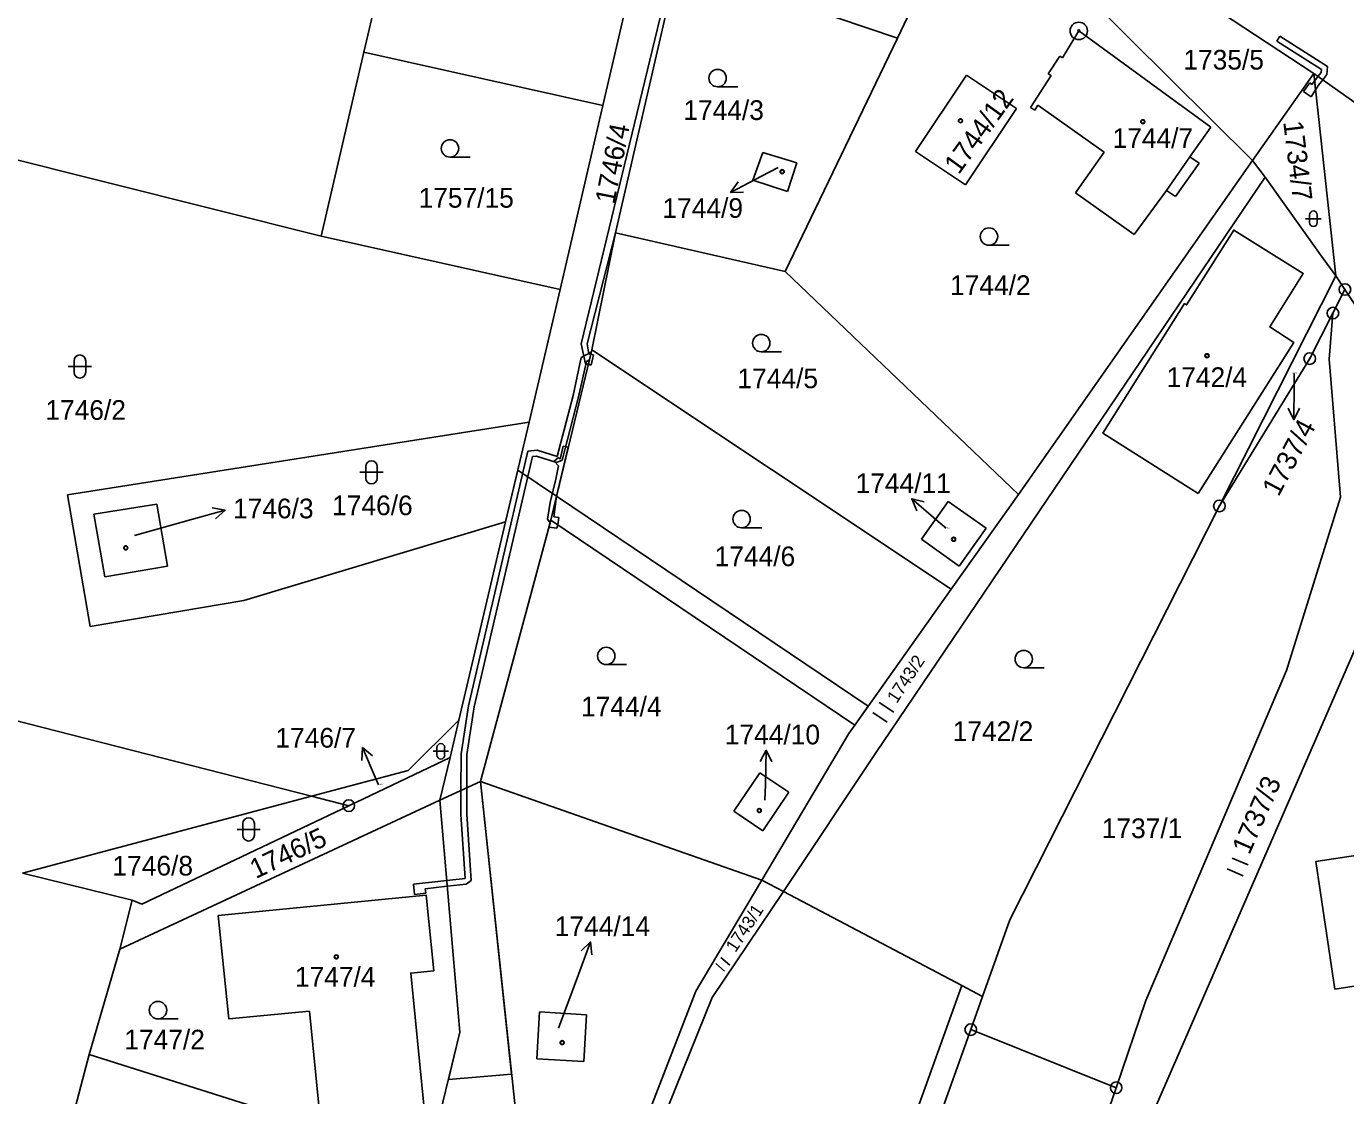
# Model space of a CAD drawing. Extents: x -593183 to -588034, y -1130415 to -1124994.
# Drawn here: x -590181.7 to -590067.9, y -1129255 to -1129162.7 of the extents above; entities that cross this region are included whole.
import ezdxf

# ---------------------------------------------------------------- set-up
doc = ezdxf.new("R2010")
doc.units = 0
for name, color, linetype in [('Vrstva 1', 7, 'Continuous'), ('Vrstva 16', 7, 'Continuous'), ('Vrstva 18', 7, 'Continuous'), ('Vrstva 19', 7, 'Continuous'), ('Vrstva 24', 7, 'Continuous'), ('Vrstva 25', 7, 'Continuous'), ('Vrstva 27', 7, 'Continuous'), ('Vrstva 4', 7, 'Continuous')]:
    doc.layers.add(name, color=color, linetype=linetype)

msp = doc.modelspace()

# ---------------------------------------------------------------- linework, layer by layer
at = {"layer": 'Vrstva 1'}
for p, q in [((-590148.57, -1129147.54), (-590152.62, -1129164.94)), ((-590070.68, -1129166.79), (-590098.81, -1129148.21)), ((-590127.57, -1129150.41), (-590132.01, -1129169.54)), ((-590100.32, -1129150.66), (-590106.6, -1129163.72)), ((-590096.22, -1129154.18), (-590075.96, -1129174.3)), ((-590125.59, -1129157.3), (-590130.92, -1129180.52)), ((-590125.59, -1129157.3), (-590106.6, -1129163.72)), ((-590092.35, -1129165.44), (-590090.95, -1129163.1)), ((-590090.95, -1129163.1), (-590079.55, -1129171.42)), ((-590106.6, -1129163.72), (-590116.28, -1129183.88)), ((-590152.62, -1129164.94), (-590156.32, -1129180.83)), ((-590132.01, -1129169.54), (-590152.62, -1129164.94)), ((-590093.59, -1129166.8), (-590092.59, -1129165.27)), ((-590092.59, -1129165.27), (-590092.35, -1129165.44)), ((-590105.05, -1129173.52), (-590100.65, -1129166.92)), ((-590100.65, -1129166.92), (-590096.33, -1129169.81)), ((-590095.11, -1129169.7), (-590093.34, -1129166.96)), ((-590093.34, -1129166.96), (-590093.59, -1129166.8)), ((-590070.68, -1129166.79), (-590075.96, -1129174.3)), ((-590061.44, -1129173.32), (-590070.68, -1129166.79)), ((-590070.68, -1129166.79), (-590068.77, -1129184.25)), ((-590135.69, -1129185.42), (-590132.01, -1129169.54)), ((-590096.33, -1129169.81), (-590100.72, -1129176.38)), ((-590094.75, -1129169.94), (-590095.11, -1129169.7)), ((-590094.48, -1129169.52), (-590094.75, -1129169.94)), ((-590088.75, -1129173.57), (-590094.48, -1129169.52)), ((-590079.55, -1129171.42), (-590081.36, -1129173.96)), ((-590156.32, -1129180.83), (-590185.45, -1129173.52)), ((-590119.06, -1129175.99), (-590118.2, -1129173.6)), ((-590118.2, -1129173.6), (-590115.28, -1129174.48)), ((-590115.28, -1129174.48), (-590116.08, -1129176.95)), ((-590100.72, -1129176.38), (-590105.05, -1129173.52)), ((-590075.96, -1129174.3), (-590096.15, -1129203.12)), ((-590091.24, -1129177.09), (-590088.75, -1129173.57)), ((-590080.58, -1129174.52), (-590082.62, -1129177.39)), ((-590081.36, -1129173.96), (-590080.58, -1129174.52)), ((-590075.96, -1129174.3), (-590074.88, -1129175.74)), ((-590074.88, -1129175.74), (-590108.53, -1129225.49)), ((-590074.88, -1129175.74), (-590070.09, -1129182.42)), ((-590116.08, -1129176.95), (-590119.06, -1129175.99)), ((-590083.38, -1129176.88), (-590086.18, -1129180.67)), ((-590082.62, -1129177.39), (-590083.38, -1129176.88)), ((-590086.18, -1129180.67), (-590091.24, -1129177.09)), ((-590135.69, -1129185.42), (-590156.32, -1129180.83)), ((-590130.92, -1129180.52), (-590132.96, -1129190.63)), ((-590116.28, -1129183.88), (-590130.92, -1129180.52)), ((-590070.09, -1129182.42), (-590068.77, -1129184.25)), ((-590116.28, -1129183.88), (-590096.15, -1129203.12)), ((-590078.82, -1129204.1), (-590068.77, -1129184.25)), ((-590068.77, -1129184.25), (-590067.99, -1129185.42)), ((-590138.38, -1129196.87), (-590135.69, -1129185.42)), ((-590069.03, -1129187.46), (-590067.99, -1129185.42)), ((-590067.99, -1129185.42), (-590066.07, -1129188.29)), ((-590071.03, -1129191.39), (-590069.03, -1129187.46)), ((-590069.35, -1129191.44), (-590069.03, -1129187.46)), ((-590132.96, -1129190.63), (-590136.51, -1129205.34)), ((-590101.95, -1129211.29), (-590132.96, -1129190.63)), ((-590078.82, -1129204.1), (-590071.03, -1129191.39)), ((-590068.36, -1129203.33), (-590069.35, -1129191.44)), ((-590178.21, -1129203.13), (-590138.38, -1129196.87)), ((-590138.38, -1129196.87), (-590140.4, -1129205.47)), ((-590176.25, -1129214.5), (-590178.21, -1129203.13)), ((-590175.92, -1129204.8), (-590170.49, -1129203.95)), ((-590170.49, -1129203.95), (-590169.56, -1129209.3)), ((-590104.53, -1129206.98), (-590102.22, -1129203.72)), ((-590102.22, -1129203.72), (-590098.95, -1129206.03)), ((-590096.15, -1129203.12), (-590101.95, -1129211.29)), ((-590096.9, -1129239.83), (-590078.82, -1129204.1)), ((-590073.04, -1129218.29), (-590068.36, -1129203.33)), ((-590174.97, -1129210.21), (-590175.92, -1129204.8)), ((-590136.51, -1129205.34), (-590142.56, -1129227.89)), ((-590136.51, -1129205.34), (-590110.27, -1129223.01)), ((-590162.98, -1129212.25), (-590140.4, -1129205.47)), ((-590140.4, -1129205.47), (-590144.43, -1129222.58)), ((-590098.95, -1129206.03), (-590101.27, -1129209.3)), ((-590062.71, -1129206.31), (-590085.14, -1129257.82)), ((-590101.27, -1129209.3), (-590104.53, -1129206.98)), ((-590169.56, -1129209.3), (-590174.97, -1129210.21)), ((-590110.27, -1129223.01), (-590101.95, -1129211.29)), ((-590176.25, -1129214.5), (-590162.98, -1129212.25)), ((-590157.14, -1129229.15), (-590204.76, -1129217)), ((-590085.16, -1129246.79), (-590073.04, -1129218.29)), ((-590148.8, -1129226.93), (-590144.43, -1129222.58)), ((-590145.19, -1129225.82), (-590144.43, -1129222.58)), ((-590110.27, -1129223.01), (-590110.8, -1129223.75)), ((-590110.8, -1129223.75), (-590118.29, -1129236.39)), ((-590153.93, -1129229.97), (-590145.19, -1129225.82)), ((-590146.07, -1129229.49), (-590145.19, -1129225.82)), ((-590108.53, -1129225.49), (-590116.42, -1129237.38)), ((-590157.14, -1129229.15), (-590148.8, -1129226.93)), ((-590142.56, -1129227.89), (-590146.07, -1129229.49)), ((-590118.29, -1129236.39), (-590142.56, -1129227.89)), ((-590139.32, -1129258.37), (-590142.56, -1129227.89)), ((-590120.71, -1129230.45), (-590118.47, -1129227.13)), ((-590118.47, -1129227.13), (-590115.98, -1129228.81)), ((-590182.08, -1129235.8), (-590157.14, -1129229.15)), ((-590153.93, -1129229.97), (-590157.14, -1129229.15)), ((-590115.98, -1129228.81), (-590118.22, -1129232.13)), ((-590173.67, -1129242.36), (-590146.07, -1129229.49)), ((-590171.78, -1129238.46), (-590153.93, -1129229.97)), ((-590146.07, -1129229.49), (-590144.34, -1129249.52)), ((-590118.22, -1129232.13), (-590120.71, -1129230.45)), ((-590070.49, -1129234.78), (-590064.46, -1129233.89)), ((-590068.87, -1129245.8), (-590070.49, -1129234.78)), ((-590182.08, -1129235.8), (-590172.61, -1129238.14)), ((-590118.29, -1129236.39), (-590123.98, -1129245.98)), ((-590118.29, -1129236.39), (-590116.42, -1129237.38)), ((-590172.61, -1129238.14), (-590173.67, -1129242.36)), ((-590172.61, -1129238.14), (-590171.78, -1129238.46)), ((-590116.42, -1129237.38), (-590122.58, -1129246.52)), ((-590116.42, -1129237.38), (-590101.05, -1129245.5)), ((-590099.25, -1129246.45), (-590096.9, -1129239.83)), ((-590176.32, -1129251.44), (-590173.67, -1129242.36)), ((-590057.4, -1129244.07), (-590068.87, -1129245.8)), ((-590123.98, -1129245.98), (-590137.75, -1129281.48)), ((-590101.05, -1129245.5), (-590099.25, -1129246.45)), ((-590122.58, -1129246.52), (-590141.38, -1129293.17)), ((-590099.25, -1129246.45), (-590100.27, -1129249.3)), ((-590085.16, -1129246.79), (-590087.73, -1129254.31)), ((-590137.7, -1129251.83), (-590137.47, -1129247.75)), ((-590137.47, -1129247.75), (-590133.43, -1129248.01)), ((-590133.43, -1129248.01), (-590133.66, -1129252.06)), ((-590144.34, -1129249.52), (-590147.06, -1129260.69)), ((-590100.27, -1129249.3), (-590119.9, -1129304.04)), ((-590100.27, -1129249.3), (-590087.73, -1129254.31)), ((-590178.2, -1129258.58), (-590176.32, -1129251.44)), ((-590147.06, -1129260.69), (-590176.32, -1129251.44)), ((-590133.66, -1129252.06), (-590137.7, -1129251.83)), ((-590087.73, -1129254.31), (-590092.79, -1129269.08))]:
    msp.add_line(p, q, dxfattribs=at)
for points in [[(-590080.66, -1129203.03), (-590088.88, -1129197.81), (-590081.83, -1129186.64), (-590081.65, -1129186.75), (-590077.58, -1129180.29), (-590071.59, -1129184.05), (-590074.47, -1129188.65), (-590072.41, -1129190), (-590080.66, -1129203.03)], [(-590147.47, -1129255.82), (-590156.42, -1129256.7), (-590157.33, -1129247.71), (-590164.27, -1129248.37), (-590165.19, -1129239.46), (-590147.25, -1129237.7), (-590146.6, -1129244.22), (-590148.59, -1129244.42), (-590147.47, -1129255.82)]]:
    msp.add_lwpolyline(points, dxfattribs=at)
at = {"layer": 'Vrstva 16'}
for p, q in [((-590116.9, -1129174.9), (-590118.33, -1129175.65)), ((-590072.37, -1129192.68), (-590072.38, -1129193.67)), ((-590172.43, -1129206.66), (-590167.5, -1129205.28)), ((-590102.4, -1129206.03), (-590103.09, -1129205.44)), ((-590151.37, -1129228.17), (-590151.56, -1129227.72)), ((-590118.03, -1129229.5), (-590117.99, -1129228.18)), ((-590135.85, -1129249.16), (-590134.12, -1129244.54))]:
    msp.add_line(p, q, dxfattribs=at)
at = {"layer": 'Vrstva 24'}
for centre, radius in [((-590090.95, -1129163.1), 0.75), ((-590090.95, -1129163.1), 0.0903), ((-590067.99, -1129185.42), 0.5), ((-590067.99, -1129185.42), 0.0327), ((-590069.03, -1129187.46), 0.5), ((-590069.03, -1129187.46), 0.0327), ((-590071.03, -1129191.39), 0.5), ((-590071.03, -1129191.39), 0.0327), ((-590078.82, -1129204.1), 0.5), ((-590078.82, -1129204.1), 0.0327), ((-590153.93, -1129229.97), 0.5), ((-590153.93, -1129229.97), 0.0327), ((-590100.27, -1129249.3), 0.5), ((-590100.27, -1129249.3), 0.0327), ((-590087.73, -1129254.31), 0.5), ((-590087.73, -1129254.31), 0.0327)]:
    msp.add_circle(centre, radius, dxfattribs=at)
at = {"layer": 'Vrstva 25'}
for p, q in [((-590120.36, -1129167.93), (-590122.11, -1129167.93)), ((-590143.45, -1129174), (-590145.2, -1129174)), ((-590118.33, -1129175.65), (-590120.99, -1129177.04)), ((-590071.05, -1129179.65), (-590071.05, -1129178.98)), ((-590070.38, -1129178.98), (-590070.38, -1129179.65)), ((-590071.38, -1129179.31), (-590070.04, -1129179.31)), ((-590096.95, -1129181.6), (-590098.7, -1129181.6)), ((-590177.63, -1129192.57), (-590177.63, -1129191.57)), ((-590176.63, -1129191.57), (-590176.63, -1129192.57)), ((-590116.6, -1129190.8), (-590118.35, -1129190.8)), ((-590178.13, -1129192.07), (-590176.13, -1129192.07)), ((-590072.38, -1129193.67), (-590072.41, -1129196.67)), ((-590152.47, -1129201.7), (-590152.47, -1129200.7)), ((-590151.47, -1129200.7), (-590151.47, -1129201.7)), ((-590152.97, -1129201.2), (-590150.97, -1129201.2)), ((-590103.09, -1129205.44), (-590105.36, -1129203.48)), ((-590167.5, -1129205.28), (-590164.61, -1129204.47)), ((-590118.29, -1129205.99), (-590120.04, -1129205.99)), ((-590129.97, -1129217.8), (-590131.72, -1129217.8)), ((-590093.95, -1129218.07), (-590095.7, -1129218.07)), ((-590106.91, -1129221.9), (-590108.16, -1129221.07)), ((-590108.72, -1129221.92), (-590107.47, -1129222.75)), ((-590151.56, -1129227.72), (-590152.74, -1129224.96)), ((-590146.66, -1129225.28), (-590145.32, -1129225.28)), ((-590146.33, -1129225.61), (-590146.33, -1129224.95)), ((-590145.66, -1129224.95), (-590145.66, -1129225.61)), ((-590117.99, -1129228.18), (-590117.91, -1129225.18)), ((-590163.07, -1129232.52), (-590163.07, -1129231.52)), ((-590162.07, -1129231.52), (-590162.07, -1129232.52)), ((-590163.57, -1129232.02), (-590161.57, -1129232.02)), ((-590076.35, -1129235.09), (-590077.73, -1129234.49)), ((-590078.14, -1129235.43), (-590076.76, -1129236.03)), ((-590134.12, -1129244.54), (-590133.07, -1129241.73)), ((-590122.27, -1129243.58), (-590121.52, -1129244.25)), ((-590121.07, -1129243.73), (-590121.82, -1129243.07)), ((-590168.64, -1129248.37), (-590170.39, -1129248.37))]:
    msp.add_line(p, q, dxfattribs=at)
for points in [[(-590119.87, -1129177.02), (-590120.99, -1129177.04), (-590120.33, -1129176.13)], [(-590071.9, -1129195.67), (-590072.41, -1129196.67), (-590072.9, -1129195.67)], [(-590104.93, -1129204.51), (-590105.36, -1129203.48), (-590104.28, -1129203.76)], [(-590165.71, -1129204.26), (-590164.61, -1129204.47), (-590165.44, -1129205.22)], [(-590152.8, -1129226.08), (-590152.74, -1129224.96), (-590151.89, -1129225.68)], [(-590118.43, -1129226.17), (-590117.91, -1129225.18), (-590117.43, -1129226.19)], [(-590133.89, -1129242.49), (-590133.07, -1129241.73), (-590132.95, -1129242.84)]]:
    msp.add_lwpolyline(points, dxfattribs=at)
for centre, radius in [((-590122.11, -1129167.18), 0.75), ((-590101.16, -1129170.86), 0.175), ((-590101.16, -1129170.86), 0.15), ((-590085.43, -1129170.94), 0.175), ((-590085.43, -1129170.94), 0.15), ((-590145.2, -1129173.25), 0.75), ((-590116.54, -1129175.25), 0.175), ((-590116.54, -1129175.25), 0.15), ((-590098.7, -1129180.85), 0.75), ((-590118.35, -1129190.05), 0.75), ((-590079.89, -1129191.14), 0.175), ((-590079.89, -1129191.14), 0.15), ((-590120.04, -1129205.24), 0.75), ((-590173.17, -1129207.72), 0.175), ((-590173.17, -1129207.72), 0.15), ((-590101.75, -1129206.98), 0.175), ((-590101.75, -1129206.98), 0.15), ((-590131.72, -1129217.05), 0.75), ((-590095.7, -1129217.32), 0.75), ((-590118.52, -1129230.39), 0.175), ((-590118.52, -1129230.39), 0.15), ((-590155.01, -1129243.02), 0.175), ((-590155.01, -1129243.02), 0.15), ((-590170.39, -1129247.62), 0.75), ((-590135.52, -1129250.42), 0.175), ((-590135.52, -1129250.42), 0.15)]:
    msp.add_circle(centre, radius, dxfattribs=at)
for centre, radius, start, end in [((-590070.71, -1129178.98), 0.335, 90, 180), ((-590070.71, -1129178.98), 0.335, 0, 90), ((-590070.71, -1129179.65), 0.335, 180, 270), ((-590070.71, -1129179.65), 0.335, 270, 0), ((-590177.13, -1129191.57), 0.5, 90, 180), ((-590177.13, -1129191.57), 0.5, 0, 90), ((-590177.13, -1129192.57), 0.5, 180, 270), ((-590177.13, -1129192.57), 0.5, 270, 0), ((-590151.97, -1129200.7), 0.5, 90, 180), ((-590151.97, -1129200.7), 0.5, 0, 90), ((-590151.97, -1129201.7), 0.5, 180, 270), ((-590151.97, -1129201.7), 0.5, 270, 0), ((-590145.99, -1129224.95), 0.335, 90, 180), ((-590145.99, -1129224.95), 0.335, 0, 90), ((-590145.99, -1129225.61), 0.335, 180, 270), ((-590145.99, -1129225.61), 0.335, 270, 0), ((-590162.57, -1129231.52), 0.5, 90, 180), ((-590162.57, -1129231.52), 0.5, 0, 90), ((-590162.57, -1129232.52), 0.5, 180, 270), ((-590162.57, -1129232.52), 0.5, 270, 0)]:
    msp.add_arc(centre, radius, start, end, dxfattribs=at)
at = {"layer": 'Vrstva 27'}
for p, q in [((-590133.89, -1129190.11), (-590123.57, -1129147.42)), ((-590125.59, -1129157.3), (-590130.92, -1129180.52)), ((-590073.87, -1129163.98), (-590073.6, -1129163.55)), ((-590070.02, -1129166.43), (-590073.87, -1129163.98)), ((-590073.6, -1129163.55), (-590069.5, -1129166.17)), ((-590070.04, -1129166.7), (-590070.02, -1129166.43)), ((-590069.5, -1129166.17), (-590069.56, -1129166.88)), ((-590071.56, -1129168.32), (-590071.03, -1129167.59)), ((-590071.03, -1129167.59), (-590070.84, -1129167.73)), ((-590070.84, -1129167.73), (-590070.61, -1129167.43)), ((-590070.61, -1129167.43), (-590070.32, -1129167.05)), ((-590070.53, -1129168.2), (-590070.61, -1129167.43)), ((-590070.61, -1129167.43), (-590070.53, -1129168.2)), ((-590070.26, -1129167.78), (-590070.53, -1129168.2)), ((-590070.32, -1129167.05), (-590070.04, -1129166.7)), ((-590069.91, -1129167.34), (-590070.26, -1129167.78)), ((-590069.56, -1129166.88), (-590069.91, -1129167.34)), ((-590070.91, -1129168.8), (-590071.56, -1129168.32)), ((-590070.53, -1129168.2), (-590070.91, -1129168.8)), ((-590130.92, -1129180.52), (-590133.37, -1129190.11)), ((-590133.5, -1129191.83), (-590133.89, -1129190.11)), ((-590133.37, -1129190.11), (-590133.21, -1129190.97)), ((-590134.58, -1129194.56), (-590133.87, -1129191.3)), ((-590133.43, -1129191.64), (-590134.1, -1129194.68)), ((-590133.87, -1129191.3), (-590133.01, -1129190.84)), ((-590133.17, -1129191.49), (-590133.43, -1129191.64)), ((-590133.05, -1129191.01), (-590133.26, -1129191.88)), ((-590133.26, -1129191.88), (-590133.05, -1129191.01)), ((-590133.21, -1129190.97), (-590133.05, -1129191.01)), ((-590133.01, -1129190.84), (-590133.17, -1129191.49)), ((-590133.05, -1129191.01), (-590132.83, -1129191.06)), ((-590132.83, -1129191.06), (-590133.03, -1129191.94)), ((-590133.26, -1129191.88), (-590133.5, -1129191.83)), ((-590133.03, -1129191.94), (-590133.26, -1129191.88)), ((-590135.95, -1129199.84), (-590134.58, -1129194.56)), ((-590134.1, -1129194.68), (-590135.51, -1129200.15)), ((-590143.6, -1129221.34), (-590138.48, -1129199.37)), ((-590138.48, -1129199.37), (-590137.67, -1129199.3)), ((-590137.67, -1129199.3), (-590135.95, -1129199.84)), ((-590134.99, -1129199.03), (-590136.01, -1129203.26)), ((-590135.69, -1129200.07), (-590135.44, -1129198.94)), ((-590135.44, -1129198.94), (-590134.99, -1129199.03)), ((-590138.08, -1129199.84), (-590143.1, -1129221.44)), ((-590137.73, -1129199.8), (-590138.08, -1129199.84)), ((-590136.02, -1129200.34), (-590137.73, -1129199.8)), ((-590136.21, -1129200.25), (-590135.85, -1129199.91)), ((-590135.83, -1129200.64), (-590136.21, -1129200.25)), ((-590136.08, -1129201.78), (-590135.83, -1129200.64)), ((-590135.51, -1129200.15), (-590136.02, -1129200.34)), ((-590135.85, -1129199.91), (-590135.69, -1129200.07)), ((-590140.4, -1129205.47), (-590139.35, -1129201.01)), ((-590139.35, -1129201.01), (-590136.01, -1129203.26)), ((-590136.56, -1129203.81), (-590136.08, -1129201.78)), ((-590136.79, -1129205.25), (-590136.56, -1129203.81)), ((-590136.01, -1129203.26), (-590136.51, -1129205.34)), ((-590136.51, -1129205.34), (-590136.01, -1129203.26)), ((-590136.51, -1129205.34), (-590136.01, -1129203.26)), ((-590136.01, -1129203.26), (-590136.51, -1129205.34)), ((-590136.01, -1129203.26), (-590136.25, -1129205.04)), ((-590136.01, -1129203.26), (-590109.12, -1129221.39)), ((-590136.51, -1129205.34), (-590142.56, -1129227.89)), ((-590136.57, -1129205.57), (-590136.79, -1129205.25)), ((-590136.51, -1129205.34), (-590136.57, -1129205.57)), ((-590136.57, -1129205.57), (-590136.51, -1129205.34)), ((-590110.27, -1129223.01), (-590136.51, -1129205.34)), ((-590135.91, -1129205.74), (-590136.51, -1129205.34)), ((-590136.51, -1129205.34), (-590135.91, -1129205.74)), ((-590136.25, -1129205.04), (-590135.8, -1129205.11)), ((-590135.8, -1129205.11), (-590135.91, -1129205.74)), ((-590144.43, -1129222.58), (-590140.4, -1129205.47)), ((-590136.67, -1129205.92), (-590136.57, -1129205.57)), ((-590135.97, -1129206.03), (-590136.67, -1129205.92)), ((-590135.91, -1129205.74), (-590135.97, -1129206.03)), ((-590144.24, -1129225.51), (-590143.6, -1129221.34)), ((-590143.1, -1129221.44), (-590143.74, -1129225.55)), ((-590109.12, -1129221.39), (-590110.27, -1129223.01)), ((-590145.19, -1129225.82), (-590144.43, -1129222.58)), ((-590146.07, -1129229.49), (-590145.19, -1129225.82)), ((-590144.25, -1129228.66), (-590144.24, -1129225.51)), ((-590143.74, -1129225.55), (-590143.75, -1129228.43)), ((-590142.56, -1129227.89), (-590146.07, -1129229.49)), ((-590146.07, -1129229.49), (-590142.56, -1129227.89)), ((-590142.56, -1129227.89), (-590139.88, -1129253.13)), ((-590143.75, -1129228.43), (-590144.25, -1129228.66)), ((-590144.25, -1129228.66), (-590143.75, -1129228.43)), ((-590144.25, -1129230.73), (-590144.25, -1129228.66)), ((-590143.75, -1129228.43), (-590143.75, -1129230.71)), ((-590144.34, -1129249.52), (-590146.07, -1129229.49)), ((-590143.89, -1129236.25), (-590144.25, -1129230.73)), ((-590143.75, -1129230.71), (-590143.38, -1129236.42)), ((-590148.35, -1129236.75), (-590145.47, -1129236.43)), ((-590148.26, -1129237.63), (-590148.35, -1129236.75)), ((-590145.43, -1129236.93), (-590147.33, -1129237.14)), ((-590147.33, -1129237.14), (-590147.29, -1129237.53)), ((-590145.47, -1129236.43), (-590143.89, -1129236.25)), ((-590145.43, -1129236.93), (-590145.47, -1129236.43)), ((-590145.47, -1129236.43), (-590145.43, -1129236.93)), ((-590143.8, -1129236.74), (-590145.43, -1129236.93)), ((-590143.38, -1129236.42), (-590143.8, -1129236.74)), ((-590147.29, -1129237.53), (-590148.26, -1129237.63)), ((-590145.34, -1129253.61), (-590144.34, -1129249.52)), ((-590139.88, -1129253.13), (-590145.34, -1129253.61))]:
    msp.add_line(p, q, dxfattribs=at)
at = {"layer": 'Vrstva 4'}
for p, q in [((-590081.36, -1129173.96), (-590083.38, -1129176.88)), ((-590122.33, -1129304.88), (-590101.05, -1129245.5))]:
    msp.add_line(p, q, dxfattribs=at)

# ---------------------------------------------------------------- texts
at = {"layer": 'Vrstva 16'}
for s, p in [('1744/9', (-590126.87, -1129179.24)), ('1744/11', (-590110.21, -1129202.99)), ('1746/3', (-590163.92, -1129205.17)), ('1746/7', (-590160.26, -1129224.96)), ('1744/10', (-590121.49, -1129224.68)), ('1744/14', (-590136.16, -1129241.23))]:
    msp.add_text(s, height=1.7, dxfattribs=at).set_placement(p)
msp.add_text('1737/4', height=1.7, rotation=62.12, dxfattribs=at).set_placement((-590073.72, -1129203.37))
at = {"layer": 'Vrstva 18'}
for s, height, p in [('1735/5', 1.7, (-590081.93, -1129166.44)), ('1744/3', 1.7, (-590125.07, -1129170.79)), ('1757/15', 1.7, (-590147.91, -1129178.36)), ('1744/2', 1.7, (-590102.06, -1129185.9)), ('1744/5', 1.7, (-590120.4, -1129193.94)), ('1737/4', 0.1, (-590072.57, -1129192.68)), ('1746/2', 1.7, (-590180.11, -1129196.67)), ('1746/6', 1.7, (-590155.37, -1129204.9)), ('1744/6', 1.7, (-590122.37, -1129209.3)), ('1744/4', 1.7, (-590133.9, -1129222.27)), ('1742/2', 1.7, (-590101.83, -1129224.39)), ('1746/7', 0.1, (-590151.37, -1129228.17)), ('1737/1', 1.7, (-590088.97, -1129232.77)), ('1746/8', 1.7, (-590174.32, -1129236)), ('1747/2', 1.7, (-590173.3, -1129251.01))]:
    msp.add_text(s, height=height, dxfattribs=at).set_placement(p)
for s, height, rotation, p in [('1734/7', 1.7, 277.0284, (-590073.32, -1129170.96)), ('1746/4', 1.7, 78.851, (-590131.03, -1129178.12)), ('1743/2', 1.1, 56.5272, (-590106.66, -1129221.2)), ('1737/3', 1.7, 66.3706, (-590076.24, -1129234.28)), ('1746/5', 1.7, 25.4515, (-590161.95, -1129236.31)), ('1743/1', 1.1, 56.5272, (-590120.57, -1129242.7))]:
    msp.add_text(s, height=height, rotation=rotation, dxfattribs=at).set_placement(p)
at = {"layer": 'Vrstva 19'}
msp.add_text('1744/12', height=1.7, rotation=54, dxfattribs=at).set_placement((-590101.31, -1129175.57))
for s, height, p in [('1744/7', 1.7, (-590088.04, -1129173.2)), ('1744/9', 0.01, (-590116.9, -1129174.9)), ('1742/4', 1.7, (-590083.38, -1129193.84)), ('1744/11', 0.1, (-590102.59, -1129206.03)), ('1746/3', 0.01, (-590172.43, -1129206.66)), ('1744/10', 0.01, (-590118.03, -1129229.5)), ('1747/4', 1.7, (-590158.58, -1129245.59)), ('1744/14', 0.01, (-590135.85, -1129249.16))]:
    msp.add_text(s, height=height, dxfattribs=at).set_placement(p)

doc.saveas('drawing.dxf')
